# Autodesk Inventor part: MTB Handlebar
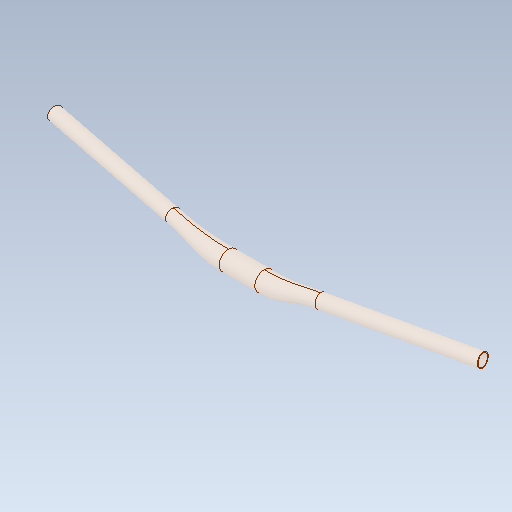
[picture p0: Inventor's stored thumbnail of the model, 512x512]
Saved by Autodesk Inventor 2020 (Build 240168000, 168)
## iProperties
Created: 2017-09
Part Number: MTB Handlebar
Material: solidworks materials|Ti-6Al-2Sn-2Zr-2Mo-2Cr-0.25Si (SS)|204
Document SubType Name: Modeling
Designer: Tomasz
Density: 4.65 g/cm^3
Appearance: 255,244,237
Sending System: SolidWorks 2017
Last Author: Tomasz
Last Saved: 2017-11-20
Author: Tomasz
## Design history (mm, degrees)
feature "Imported1"
node "Bryła1"
